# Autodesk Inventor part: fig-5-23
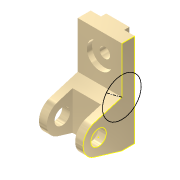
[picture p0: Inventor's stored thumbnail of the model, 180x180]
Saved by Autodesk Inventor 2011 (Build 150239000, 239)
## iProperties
Shininess: 65.0
Angle Display Precision: 2
Document Length Units: 11269
Document Angle Units: 11279
Document Time Units: 11290
Document Mass Units: 11283
Document Length Units Precision: 3
Document Angle Units Precision: 2
Compacted: False
Created: 2001-11
Part Number: fig-5-23
Document SubType Name: Modeling
Designer: Renu Muthoo
Density: 1 g/cm^3
Density: 0.0
Volumn: 0.0
Area: 0.0
PropertySet Name: Model Information
Control State: 0
Master: False
Checked Out: False
Author: Renu Muthoo
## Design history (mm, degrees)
node "Sketch1"
sketch "Sketch2"
  geometry: L1 (33.257, 104.664)-(33.257, -75.336); L2 (33.257, -75.336)-(8.257, -75.336); L3 (8.257, -75.336)-(-45.451, -59.045); L4 (-45.451, -1.628)-(8.257, 14.664); L5 (8.257, 14.664)-(8.257, 104.664); L6 (8.257, 104.664)-(33.257, 104.664); C1 r 15 at (-36.743, -30.336); A1 r 30 centre (-36.743, -30.336) between (-45.451, -1.628) and (-45.451, -59.045)
  constraints: 12 end point, 2 centre point, 2 equal length, 2 parallel, 2 point on circle, 2 tangent, 1 coincident, 1 perpendicular, 1 vertical
  dimensions: "d0" = 180 distance of L1.start L1.end; "d1" = 30 radius of A1; "d2" = 25 distance of L5.end L1.start; "d3" = 45 distance from line of L2 A1.centre; "d4" = 70 distance from line of L1 A1.centre; "d5" = 30 diameter of C1
extrude "Extrusion1" new body sketch "Sketch2" distance "d6" = 85; taper "d7" = 0 deg
workplane "Work Plane1"
sketch "Sketch3"
  geometry: L1 (15, 62.364)-(70, 62.364); L2 (70, 62.364)-(70, -52.386); L3 (70, -52.386)-(15, -52.386); L4 (15, -52.386)-(15, 62.364); L5 (0, -45)-(0, -28.708) reference
  constraints: 8 end point, 2 parallel, 1 horizontal, 1 perpendicular
  dimensions: "d8" = 55 distance of L1.start L1.end; "d9" = 15 distance between parallel lines of L5 L4
extrude "Extrusion2" cut sketch "Sketch3" distance "d10" = 50; taper "d11" = 0 deg
sketch "Sketch4"
  geometry: L1 (0, 25)-(85, 25) reference; L2 (0, 0)-(0, 25) reference; L3 (20, 25)-(65, 25); L4 (65, 25)-(65, 35); L5 (65, 35)-(20, 35); L6 (20, 35)-(20, 25)
  constraints: 8 end point, 2 parallel, 1 horizontal, 1 perpendicular, 1 point on line
  dimensions: "d12" = 45 distance of L4.end L5.end; "d13" = 10 distance of L3.end L4.end; "d14" = 20 distance between parallel lines of L2 L6
extrude "Extrusion3" join sketch "Sketch4" stored distance "d15" = 50; taper "d16" = 0 deg
sketch "Sketch5"
  geometry: L1 (85, 0)-(85, 90) reference; L2 (0, 90)-(85, 90) reference; 1 further point
  dimensions: "d17" = 42 distance from line of L2 point (42.5, 48); "d18" = 42.5 distance from line of L1 point (42.5, 48)
hole "Hole1" sketch "Sketch5" at (42.5, 48) diameter "d19" = 20; stored, may be unused: countersink angle "d23" = 82 deg, drill point angle "d25" = 118 deg; dims "d20" = 6, "d21" = 50, "d22" = 10, "d24" = 8
sketch "Sketch8"
  geometry: L1 (75.336, 33.257)-(75.336, 8.257) reference; L2 (-104.664, 33.257)-(75.336, 33.257) reference; L3 (-104.664, 8.257)-(-104.664, 33.257) reference; L4 (-14.664, 8.257)-(-104.664, 8.257) reference; L5 (1.628, -45.451)-(-14.664, 8.257) reference; L6 (75.336, 8.257)-(59.045, -45.451) reference; C1 r 15 at (30.336, -36.743) reference; C2 r 37.437 at (-14.664, 8.257); A1 r 30 centre (30.336, -36.743) between (1.628, -45.451) and (59.045, -45.451) reference
  constraints: 1 centre point, 1 coincident
sketch "Sketch9"
  geometry: L1 (75.336, 33.257)-(75.336, 8.257) reference; L2 (-14.664, 8.257)-(-104.664, 8.257) reference; L3 (1.628, -45.451)-(-14.664, 8.257) reference; L4 (75.336, 8.257)-(59.045, -45.451) reference; L5 (-14.664, 8.257)-(-37, -21.743); C1 r 15 at (30.336, -36.743) reference; A1 r 30 centre (30.336, -36.743) between (1.628, -45.451) and (59.045, -45.451) reference
  constraints: 2 end point
body "Solid1"
